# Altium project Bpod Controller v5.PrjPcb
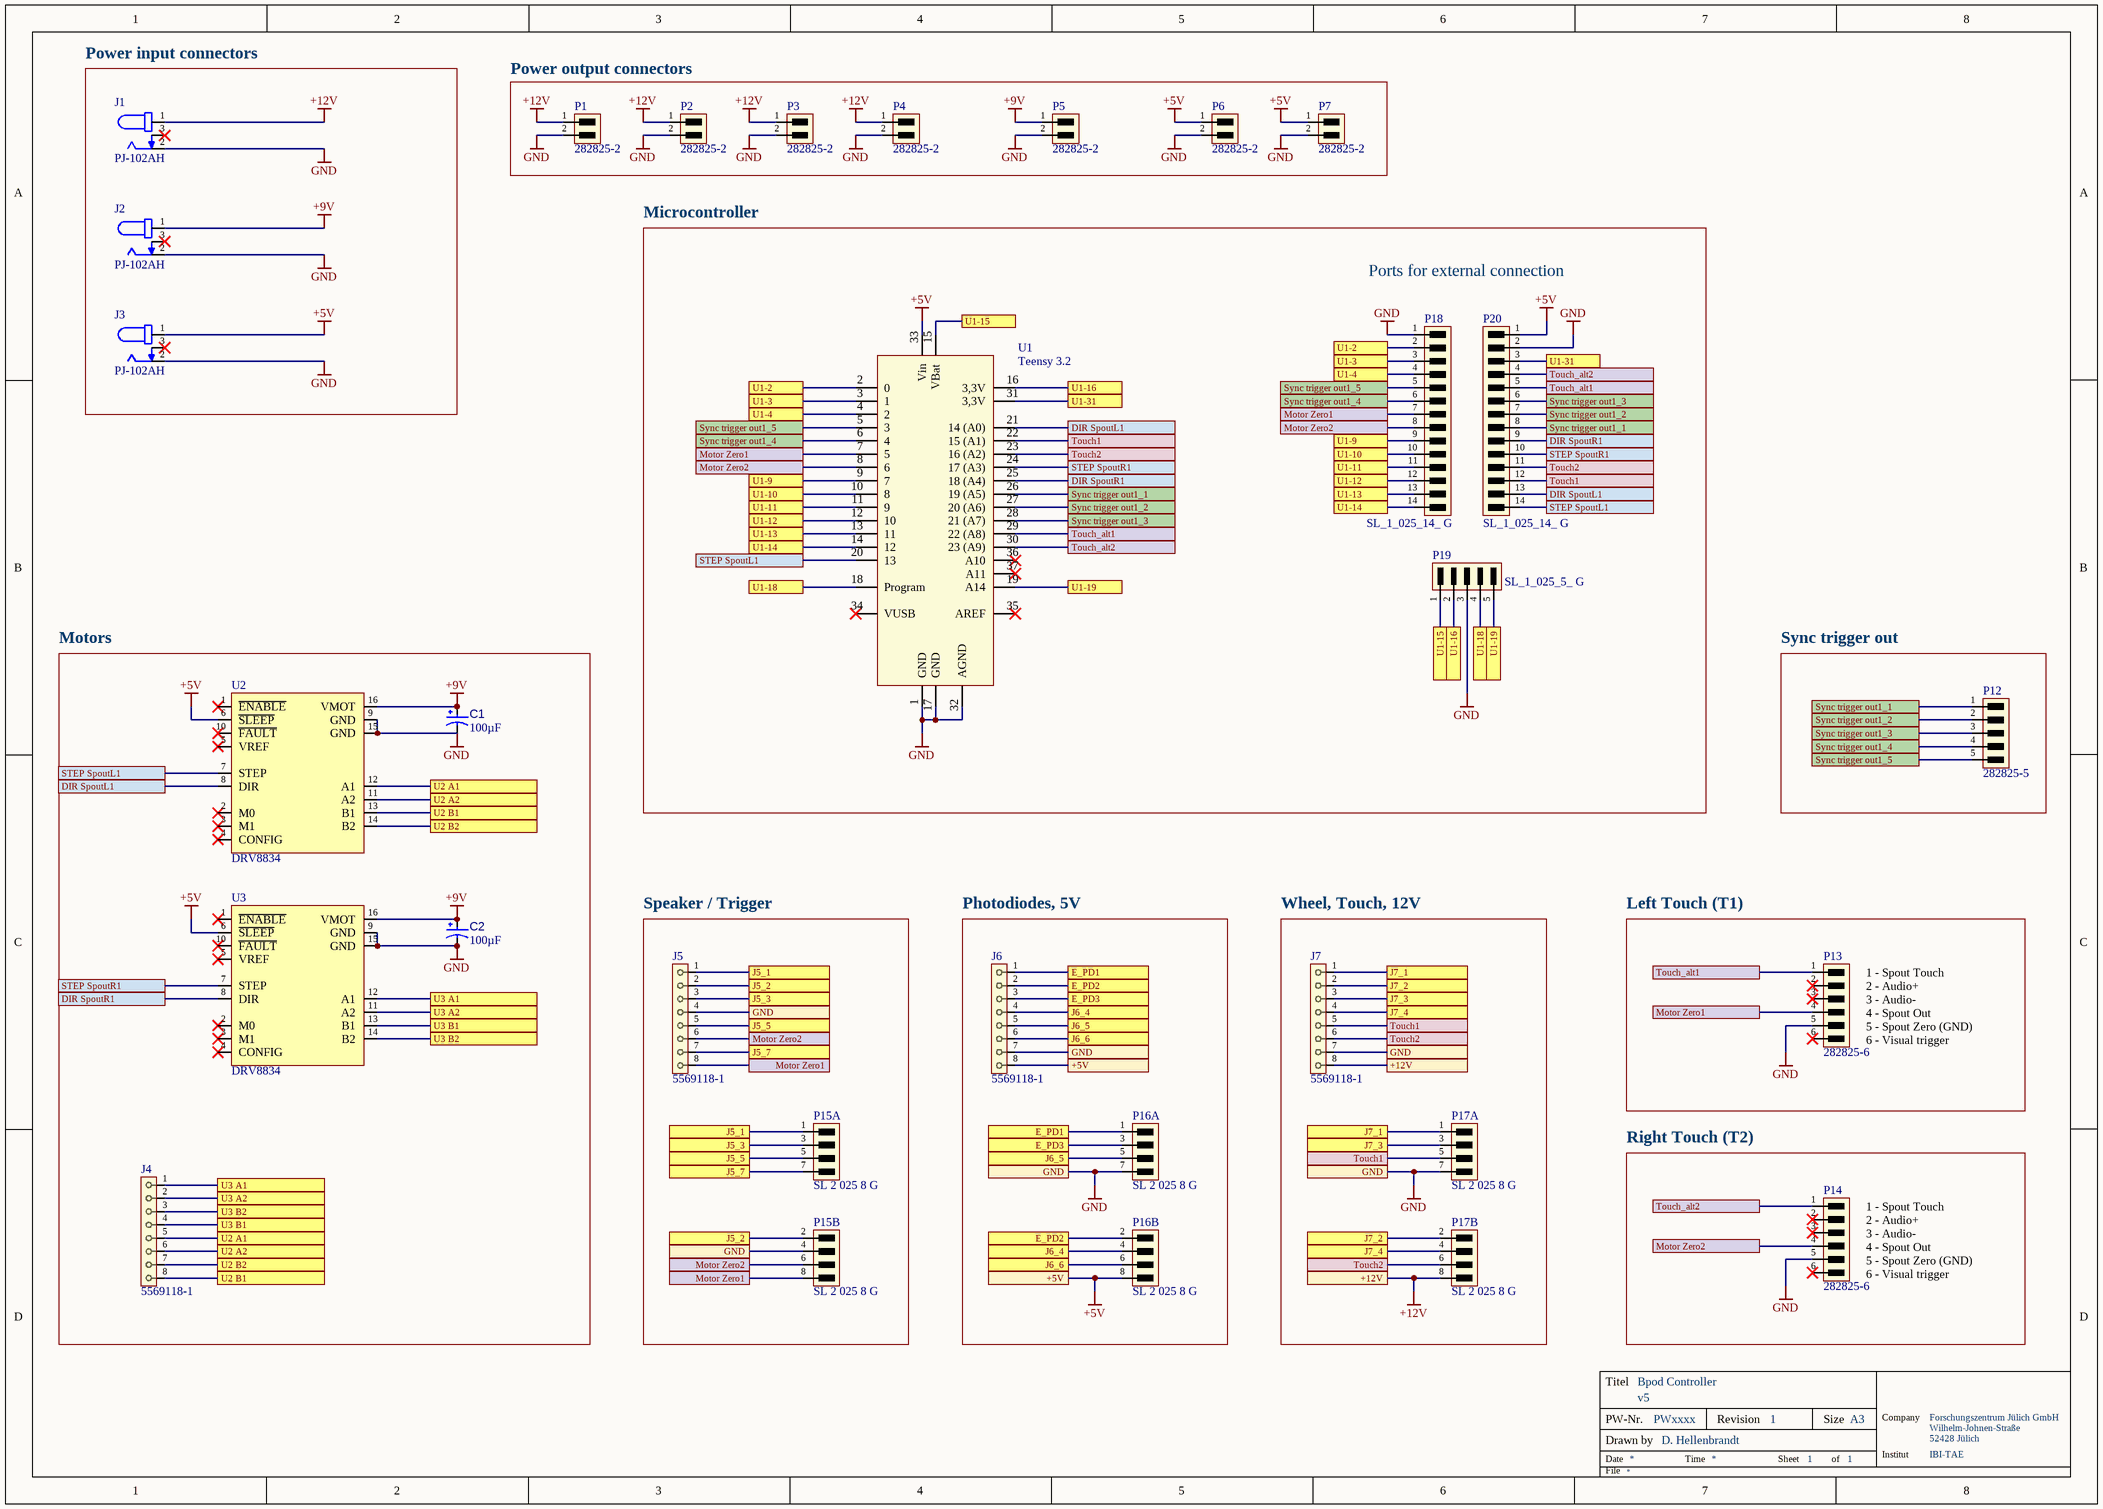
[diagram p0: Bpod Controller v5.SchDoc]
1 sheet, 28 parts. Net scope: flat (ports and power ports of the same name join across sheets).
Board file: Bpod Controller v5.PcbDoc

## Sheet Bpod Controller v5.SchDoc: Bpod Controller
size A3; CompanyName: Forschungszentrum Jülich GmbH; DrawnBy: D. Hellenbrandt; Organization: IBI-TAE; Address1: Wilhelm-Johnen-Straße; Address2: 52428 Jülich; DocumentNumber: PWxxxx; Revision: 1; SheetNumber: 1; SheetTotal: 1; Title2: v5

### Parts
C1  value 100µF  [AVX-TAJ-C-2_M]  (hidden comment: TAJC107K016RNJ)
C2  value 100µF  [AVX-TAJ-C-2_M]  (hidden comment: TAJC107K016RNJ)
J1  PJ-102AH  [CUI_PJ-102AH]
J2  PJ-102AH  [CUI_PJ-102AH]
J3  PJ-102AH  [CUI_PJ-102AH]
J4  5569118-1  [5569118-1-Footprint-1]
J5  5569118-1  [5569118-1-Footprint-1]
J6  5569118-1  [5569118-1-Footprint-1]
J7  5569118-1  [5569118-1-Footprint-1]
P1  282825-2  [282825-4-Footprint-1]
P2  282825-2  [282825-4-Footprint-1]
P3  282825-2  [282825-4-Footprint-1]
P4  282825-2  [282825-4-Footprint-1]
P5  282825-2  [282825-4-Footprint-1]
P6  282825-2  [282825-4-Footprint-1]
P7  282825-2  [282825-4-Footprint-1]
P12  282825-5  [282825-4-Footprint-1]
P13  282825-6  [282825-4-Footprint-1]
P14  282825-6  [282825-4-Footprint-1]
P15  SL 2 025 8 G  [SL 2 025 2 G-Footprint-1]  (parts A,B of 2)
P16  SL 2 025 8 G  [SL 2 025 2 G-Footprint-1]  (parts A,B of 2)
P17  SL 2 025 8 G  [SL 2 025 2 G-Footprint-1]  (parts A,B of 2)
P18  SL_1_025_14_ G  [SL_1_025_14_ G]
P19  SL_1_025_5_ G  [SL_1_025_5_ G]
P20  SL_1_025_14_ G  [SL_1_025_14_ G]
U1  Teensy 3.2  [New footprint 1]
U2  DRV8834  [DRV8825 STEPPER MOTOR DRIVER CARRIER-Footprint-1]
U3  DRV8834  [DRV8825 STEPPER MOTOR DRIVER CARRIER-Footprint-1]

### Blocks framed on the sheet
Power input connectors: J1-J3
Power output connectors: P1-P7
Motors: C1 C2 J4 U2 U3
Sync trigger out: P12
Speaker / Trigger: J5 P15
Photodiodes, 5V: J6 P16
Wheel, Touch, 12V: J7 P17
Left Touch (T1): P13
Right Touch (T2): P14

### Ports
+5V (see Bpod Controller v5[4D]), +5V (see Bpod Controller v5[5C]), +12V (see Bpod Controller v5[5D]), +12V (see Bpod Controller v5[6C]), DIR SpoutL1 (see Bpod Controller v5[1C], Bpod Controller v5[5B]), DIR SpoutL1 (see Bpod Controller v5[1C], Bpod Controller v5[6B]), DIR SpoutL1 (see Bpod Controller v5[5B], Bpod Controller v5[6B]), DIR SpoutR1 (see Bpod Controller v5[1C], Bpod Controller v5[5B]), DIR SpoutR1 (see Bpod Controller v5[1C], Bpod Controller v5[6B]), DIR SpoutR1 (see Bpod Controller v5[5B], Bpod Controller v5[6B]), E_PD1 (see Bpod Controller v5[4D]), E_PD1 (see Bpod Controller v5[5C]), E_PD2 (see Bpod Controller v5[4D]), E_PD2 (see Bpod Controller v5[5C]), E_PD3 (see Bpod Controller v5[4D]), E_PD3 (see Bpod Controller v5[5C]), GND (see Bpod Controller v5[3C], Bpod Controller v5[3D], Bpod Controller v5[4D], Bpod Controller v5[5C], Bpod Controller v5[5D]), GND (see Bpod Controller v5[3C], Bpod Controller v5[3D], Bpod Controller v5[4D], Bpod Controller v5[5C], Bpod Controller v5[6C]), GND (see Bpod Controller v5[3C], Bpod Controller v5[3D], Bpod Controller v5[4D], Bpod Controller v5[5D], Bpod Controller v5[6C]), GND (see Bpod Controller v5[3C], Bpod Controller v5[3D], Bpod Controller v5[5C], Bpod Controller v5[5D], Bpod Controller v5[6C]), GND (see Bpod Controller v5[3C], Bpod Controller v5[4D], Bpod Controller v5[5C], Bpod Controller v5[5D], Bpod Controller v5[6C]), GND (see Bpod Controller v5[3D], Bpod Controller v5[4D], Bpod Controller v5[5C], Bpod Controller v5[5D], Bpod Controller v5[6C]), J5_1 (see Bpod Controller v5[3C]), J5_1 (see Bpod Controller v5[3D]), J5_2 (see Bpod Controller v5[3C]), J5_2 (see Bpod Controller v5[3D]), J5_3 (see Bpod Controller v5[3C]), J5_3 (see Bpod Controller v5[3D]), J5_5 (see Bpod Controller v5[3C]), J5_5 (see Bpod Controller v5[3D]), J5_7 (see Bpod Controller v5[3C]), J5_7 (see Bpod Controller v5[3D]), J6_4 (see Bpod Controller v5[4D]), J6_4 (see Bpod Controller v5[5C]), J6_5 (see Bpod Controller v5[4D]), J6_5 (see Bpod Controller v5[5C]), J6_6 (see Bpod Controller v5[4D]), J6_6 (see Bpod Controller v5[5C]), J7_1 (see Bpod Controller v5[5D]), J7_1 (see Bpod Controller v5[6C]), J7_2 (see Bpod Controller v5[5D]), J7_2 (see Bpod Controller v5[6C]), J7_3 (see Bpod Controller v5[5D]), J7_3 (see Bpod Controller v5[6C]), J7_4 (see Bpod Controller v5[5D]), J7_4 (see Bpod Controller v5[6C]), Motor Zero1 (see Bpod Controller v5[3B], Bpod Controller v5[3C], Bpod Controller v5[3D], Bpod Controller v5[5B]), Motor Zero1 (see Bpod Controller v5[3B], Bpod Controller v5[3C], Bpod Controller v5[3D], Bpod Controller v5[7C]), Motor Zero1 (see Bpod Controller v5[3B], Bpod Controller v5[3C], Bpod Controller v5[5B], Bpod Controller v5[7C]), Motor Zero1 (see Bpod Controller v5[3B], Bpod Controller v5[3D], Bpod Controller v5[5B], Bpod Controller v5[7C]), Motor Zero1 (see Bpod Controller v5[3C], Bpod Controller v5[3D], Bpod Controller v5[5B], Bpod Controller v5[7C]), Motor Zero2 (see Bpod Controller v5[3B], Bpod Controller v5[3C], Bpod Controller v5[3D], Bpod Controller v5[5B]), Motor Zero2 (see Bpod Controller v5[3B], Bpod Controller v5[3C], Bpod Controller v5[3D], Bpod Controller v5[7D]), Motor Zero2 (see Bpod Controller v5[3B], Bpod Controller v5[3C], Bpod Controller v5[5B], Bpod Controller v5[7D]), Motor Zero2 (see Bpod Controller v5[3B], Bpod Controller v5[3D], Bpod Controller v5[5B], Bpod Controller v5[7D]), Motor Zero2 (see Bpod Controller v5[3C], Bpod Controller v5[3D], Bpod Controller v5[5B], Bpod Controller v5[7D]), STEP SpoutL1 (see Bpod Controller v5[1C], Bpod Controller v5[3B]), STEP SpoutL1 (see Bpod Controller v5[1C], Bpod Controller v5[6B]), STEP SpoutL1 (see Bpod Controller v5[3B], Bpod Controller v5[6B]), STEP SpoutR1 (see Bpod Controller v5[1C], Bpod Controller v5[5B]), STEP SpoutR1 (see Bpod Controller v5[1C], Bpod Controller v5[6B]), STEP SpoutR1 (see Bpod Controller v5[5B], Bpod Controller v5[6B]), Sync trigger out1_1 (see Bpod Controller v5[5B], Bpod Controller v5[6B]), Sync trigger out1_1 (see Bpod Controller v5[5B], Bpod Controller v5[7B]), Sync trigger out1_1 (see Bpod Controller v5[6B], Bpod Controller v5[7B]), Sync trigger out1_2 (see Bpod Controller v5[5B], Bpod Controller v5[6B]), Sync trigger out1_2 (see Bpod Controller v5[5B], Bpod Controller v5[7B]), Sync trigger out1_2 (see Bpod Controller v5[6B], Bpod Controller v5[7B]), Sync trigger out1_3 (see Bpod Controller v5[5B], Bpod Controller v5[6B]), Sync trigger out1_3 (see Bpod Controller v5[5B], Bpod Controller v5[7B]), Sync trigger out1_3 (see Bpod Controller v5[6B], Bpod Controller v5[7B]), Sync trigger out1_4 (see Bpod Controller v5[3B], Bpod Controller v5[5B]), Sync trigger out1_4 (see Bpod Controller v5[3B], Bpod Controller v5[7B]), Sync trigger out1_4 (see Bpod Controller v5[5B], Bpod Controller v5[7B]), Sync trigger out1_5 (see Bpod Controller v5[3B], Bpod Controller v5[5B]), Sync trigger out1_5 (see Bpod Controller v5[3B], Bpod Controller v5[7C]), Sync trigger out1_5 (see Bpod Controller v5[5B], Bpod Controller v5[7C]), Touch1 (see Bpod Controller v5[5B], Bpod Controller v5[5D], Bpod Controller v5[6B]), Touch1 (see Bpod Controller v5[5B], Bpod Controller v5[5D], Bpod Controller v5[6C]), Touch1 (see Bpod Controller v5[5B], Bpod Controller v5[6B], Bpod Controller v5[6C]), Touch1 (see Bpod Controller v5[5D], Bpod Controller v5[6B], Bpod Controller v5[6C]), Touch2 (see Bpod Controller v5[5B], Bpod Controller v5[5D], Bpod Controller v5[6B]), Touch2 (see Bpod Controller v5[5B], Bpod Controller v5[5D], Bpod Controller v5[6C]), Touch2 (see Bpod Controller v5[5B], Bpod Controller v5[6B], Bpod Controller v5[6C]), Touch2 (see Bpod Controller v5[5D], Bpod Controller v5[6B], Bpod Controller v5[6C]), Touch_alt1 (see Bpod Controller v5[5B], Bpod Controller v5[6B]), Touch_alt1 (see Bpod Controller v5[5B], Bpod Controller v5[7C]), Touch_alt1 (see Bpod Controller v5[6B], Bpod Controller v5[7C]), Touch_alt2 (see Bpod Controller v5[5B], Bpod Controller v5[6A]), Touch_alt2 (see Bpod Controller v5[5B], Bpod Controller v5[7D]), Touch_alt2 (see Bpod Controller v5[6A], Bpod Controller v5[7D]), U1-2 (see Bpod Controller v5[3B]), U1-2 (see Bpod Controller v5[6A]), U1-3 (see Bpod Controller v5[3B]), U1-3 (see Bpod Controller v5[6A]), U1-4 (see Bpod Controller v5[3B]), U1-4 (see Bpod Controller v5[6A]), U1-9 (see Bpod Controller v5[3B]), U1-9 (see Bpod Controller v5[6B]), U1-10 (see Bpod Controller v5[3B]), U1-10 (see Bpod Controller v5[6B]), U1-11 (see Bpod Controller v5[3B]), U1-11 (see Bpod Controller v5[6B]), U1-12 (see Bpod Controller v5[3B]), U1-12 (see Bpod Controller v5[6B]), U1-13 (see Bpod Controller v5[3B]), U1-13 (see Bpod Controller v5[6B]), U1-14 (see Bpod Controller v5[3B]), U1-14 (see Bpod Controller v5[6B]), U1-15 (see Bpod Controller v5[4A]), U1-15 (see Bpod Controller v5[6B]), U1-16 (see Bpod Controller v5[5B]), U1-16 (see Bpod Controller v5[6B]), U1-18 (see Bpod Controller v5[3B]), U1-18 (see Bpod Controller v5[6B]), U1-19 (see Bpod Controller v5[5B]), U1-19 (see Bpod Controller v5[6B]), U1-31 (see Bpod Controller v5[5B]), U1-31 (see Bpod Controller v5[6A]), U2 A1 (see Bpod Controller v5[1D]), U2 A1 (see Bpod Controller v5[2C]), U2 A2 (see Bpod Controller v5[1D]), U2 A2 (see Bpod Controller v5[2C]), U2 B1 (see Bpod Controller v5[1D]), U2 B1 (see Bpod Controller v5[2C]), U2 B2 (see Bpod Controller v5[1D]), U2 B2 (see Bpod Controller v5[2C]), U3 A1 (see Bpod Controller v5[1D]), U3 A1 (see Bpod Controller v5[2C]), U3 A2 (see Bpod Controller v5[1D]), U3 A2 (see Bpod Controller v5[2C]), U3 B1 (see Bpod Controller v5[1D]), U3 B1 (see Bpod Controller v5[2C]), U3 B2 (see Bpod Controller v5[1D]), U3 B2 (see Bpod Controller v5[2C])

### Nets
+5V: J3.1 J6.8 P6.1 P7.1 P16.8 P20.1 U1.33(Vin) U2.6(~{SLEEP}) U3.6(~{SLEEP}) ; port +5V
+9V: C1.1 C2.1 J2.1 P5.1 U2.16(VMOT) U3.16(VMOT)
+12V: J1.1 J7.8 P1.1 P2.1 P3.1 P4.1 P17.8 ; port +12V
GND: C1.2 C2.2 J1.2 J2.2 J3.2 J5.4 J6.7 J7.7 P1.2 P2.2 P3.2 P4.2 P5.2 P6.2 P7.2 P13.5 P14.5 P15.4 P16.7 P17.7 P18.1 P19.3 P20.2 U1.1(GND) U1.17(GND) U1.32(AGND) U2.9(GND) U2.15(GND) U3.9(GND) U3.15(GND) ; port GND
NetJ4_1: J4.1 U3.12(A1) ; port U3 A1
NetJ4_2: J4.2 U3.11(A2) ; port U3 A2
NetJ4_3: J4.3 U3.14(B2) ; port U3 B2
NetJ4_4: J4.4 U3.13(B1) ; port U3 B1
NetJ4_5: J4.5 U2.12(A1) ; port U2 A1
NetJ4_6: J4.6 U2.11(A2) ; port U2 A2
NetJ4_7: J4.7 U2.14(B2) ; port U2 B2
NetJ4_8: J4.8 U2.13(B1) ; port U2 B1
NetJ5_1: J5.1 P15.1 ; port J5_1
NetJ5_2: J5.2 P15.2 ; port J5_2
NetJ5_3: J5.3 P15.3 ; port J5_3
NetJ5_5: J5.5 P15.5 ; port J5_5
NetJ5_6: J5.6 P14.4 P15.6 P18.8 U1.8(6) ; port Motor Zero2
NetJ5_7: J5.7 P15.7 ; port J5_7
NetJ5_8: J5.8 P13.4 P15.8 P18.7 U1.7(5) ; port Motor Zero1
NetJ6_1: J6.1 P16.1 ; port E_PD1
NetJ6_2: J6.2 P16.2 ; port E_PD2
NetJ6_3: J6.3 P16.3 ; port E_PD3
NetJ6_4: J6.4 P16.4 ; port J6_4
NetJ6_5: J6.5 P16.5 ; port J6_5
NetJ6_6: J6.6 P16.6 ; port J6_6
NetJ7_1: J7.1 P17.1 ; port J7_1
NetJ7_2: J7.2 P17.2 ; port J7_2
NetJ7_3: J7.3 P17.3 ; port J7_3
NetJ7_4: J7.4 P17.4 ; port J7_4
NetJ7_5: J7.5 P17.5 P20.12 U1.22(15_(A1)) ; port Touch1
NetJ7_6: J7.6 P17.6 P20.11 U1.23(16_(A2)) ; port Touch2
NetP12_1: P12.1 P20.8 U1.26(19_(A5)) ; port Sync trigger out1_1
NetP12_2: P12.2 P20.7 U1.27(20_(A6)) ; port Sync trigger out1_2
NetP12_3: P12.3 P20.6 U1.28(21_(A7)) ; port Sync trigger out1_3
NetP12_4: P12.4 P18.6 U1.6(4) ; port Sync trigger out1_4
NetP12_5: P12.5 P18.5 U1.5(3) ; port Sync trigger out1_5
NetP13_1: P13.1 P20.5 U1.29(22_(A8)) ; port Touch_alt1
NetP14_1: P14.1 P20.4 U1.30(23_(A9)) ; port Touch_alt2
NetP18_2: P18.2 U1.2(0) ; port U1-2
NetP18_3: P18.3 U1.3(1) ; port U1-3
NetP18_4: P18.4 U1.4(2) ; port U1-4
NetP18_9: P18.9 U1.9(7) ; port U1-9
NetP18_10: P18.10 U1.10(8) ; port U1-10
NetP18_11: P18.11 U1.11(9) ; port U1-11
NetP18_12: P18.12 U1.12(10) ; port U1-12
NetP18_13: P18.13 U1.13(11) ; port U1-13
NetP18_14: P18.14 U1.14(12) ; port U1-14
NetP19_1: P19.1 U1.15(VBat) ; port U1-15
NetP19_2: P19.2 U1.16(3,3V) ; port U1-16
NetP19_4: P19.4 U1.18(Program) ; port U1-18
NetP19_5: P19.5 U1.19(A14) ; port U1-19
NetP20_3: P20.3 U1.31(3,3V) ; port U1-31
NetP20_9: P20.9 U1.25(18_(A4)) U3.8(DIR) ; port DIR SpoutR1
NetP20_10: P20.10 U1.24(17_(A3)) U3.7(STEP) ; port STEP SpoutR1
NetP20_13: P20.13 U1.21(14_(A0)) U2.8(DIR) ; port DIR SpoutL1
NetP20_14: P20.14 U1.20(13) U2.7(STEP) ; port STEP SpoutL1

Not connected (* = marked no-connect by the designer): J1 3*; J2 3*; J3 3*; P13 2* 3* 6*; P14 2* 3* 6*; U1 34(VUSB)* 35(AREF)* 36(A10)* 37(A11)*; U2 1(~{ENABLE})* 2(M0)* 3(M1)* 4(CONFIG)* 5(VREF)* 10(~{FAULT})*; U3 1(~{ENABLE})* 2(M0)* 3(M1)* 4(CONFIG)* 5(VREF)* 10(~{FAULT})*

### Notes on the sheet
- Microcontroller
- Ports for external connection
- (near P13) 1 - Spout Touch
  2 - Audio+
  3 - Audio-
  4 - Spout Out
  5 - Spout Zero (GND)
  6 - Visual trigger
- (near P14) 1 - Spout Touch
  2 - Audio+
  3 - Audio-
  4 - Spout Out
  5 - Spout Zero (GND)
  6 - Visual trigger

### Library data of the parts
C1 C2 = CMP-001-00046-9: Standard Tantalum, 100 uF, +/- 10%, 16 V, -55 to 125 degC, 2312 (6032 Metric), RoHS, Tape and Reel; Manufacturer: AVX; Voltage Rating: 16V; Resistance: 1Ohm
J1-J3 = CMP-00027-00002-5: 12V, 2.5A, 2mm Dia; user: IBI-TAE
J4-J7 = CMP-002-00096-6: Telecom and Datacom Connector, 8 Contact(s), Female, Right Angle, Solder Terminal, Locking, Jack; User: IBI-TAE
P1-P7 = CMP-002-00093-3: Strip Terminal Block, 15A, 1 Row(s), 1 Deck(s); Gender: male; Connector Type: Pluggable Terminal Block; user: IBI-TAE; Voltage Rating: 300V
P12 = CMP-002-00091-4: Strip Terminal Block, 15A, 1 Row(s), 1 Deck(s); Connector Type: Pluggable Terminal Block; user: IBI-TAE; Gender: male; Voltage Rating: 300V
P13 P14 = CMP-002-00092-4: Strip Terminal Block, 15A, 1 Row(s), 1 Deck(s); Gender: male; Connector Type: Pluggable Terminal Block; Voltage Rating: 300V; user: IBI-TAE
P15-P17 = CMP-002-00101-2: Fischer  SL 2 025 8 G, Stiftleiste, 2 Reiheb, 8 Pole, vergoldet; Number of Rows Loaded: 2; Connector Type: BOARD CONNECTOR; Gender: male; Number of Contacts: 8; user: IBI-TAE; Voltage Rating: 300V; Max Current Rating: 3A
P18 P20 = CMP-002-00107-2: Fischer SL_1_025_14_ G, Stiftleiste, 1 Reiheb, 14 Pole, vergoldet; Max Current Rating: 3A; user: IBI-TAE; Voltage Rating: 300V; Connector Type: BOARD CONNECTOR; Number of Contacts: 14; Number of Rows Loaded: 1; Gender: male
P19 = CMP-002-00106-1: Fischer SL_1_025_5_ G, Stiftleiste, 1 Reiheb, 5 Pole, vergoldet; Max Current Rating: 3A; Voltage Rating: 300V; Gender: male; user: IBI-TAE; Number of Rows Loaded: 1; Connector Type: BOARD CONNECTOR; Number of Contacts: 5
U1 = CMP-00000-6: Development Boards & Kits, ARM Teensy 3.2 and header; user: IBI-TAE
U2 U3 = CMP-00024-00007-1: DRV8834 Low-Voltage Stepper Motor Driver Carrier; Min Supply Voltage: 2,5V; Max current per phase: 2A; Continuous current per phase: 1,5A; user: IBI-TAE; Max Supply Voltage: 10,8V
